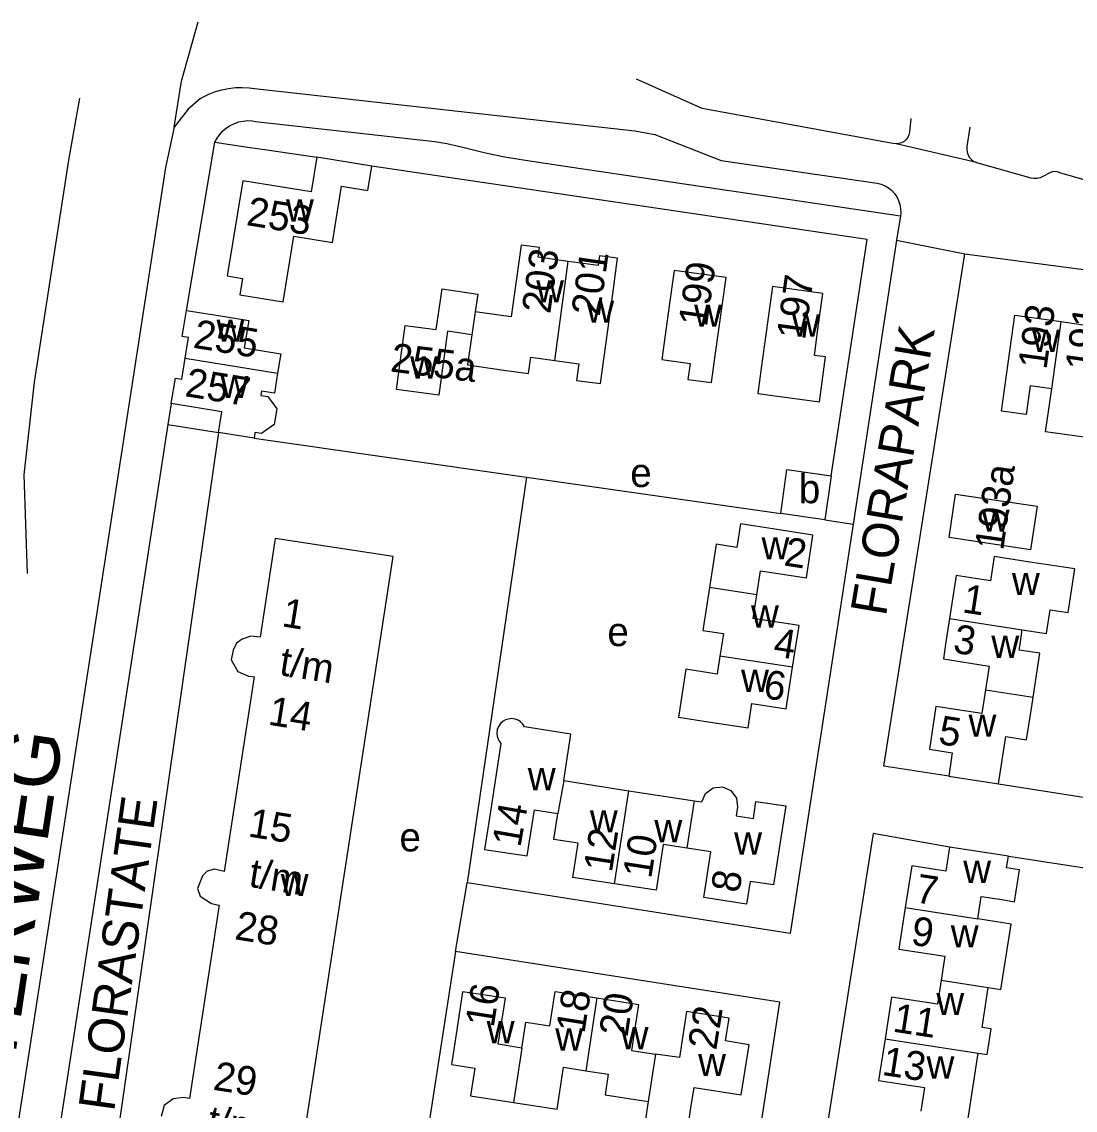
# Model space of a CAD drawing. Extents: x 161093 to 163177, y 379000 to 380904.
# Drawn here: x 161685 to 161831.1, y 380685.4 to 380836.3 of the extents above; entities that cross this region are included whole.
import ezdxf

# ---------------------------------------------------------------- set-up
doc = ezdxf.new("R2010")
doc.units = 0
for name, color, linetype in [('BLT_Basislijn', 7, 'Continuous'), ('BLT_Bebouwing', 7, 'Continuous'), ('BLT_Centroide', 7, 'Continuous'), ('BLT_Huisnummer', 7, 'Continuous'), ('BLT_Huisnummer_ tussenligend', 7, 'Continuous'), ('BLT_Huisnummer_reeks', 7, 'Continuous'), ('BLT_Onderverdeling_panden', 7, 'Continuous'), ('BLT_Straatnaam', 7, 'Continuous'), ('BLT_Straatnaam_hoofdweg', 7, 'Continuous'), ('BLT_Vlakafsluiter', 7, 'Continuous')]:
    doc.layers.add(name, color=color, linetype=linetype)

msp = doc.modelspace()

# ---------------------------------------------------------------- linework, layer by layer
at = {"layer": 'BLT_Basislijn'}
for p, q in [((161717.31, 380827.08), (161770.07, 380821.19)), ((161717.48, 380822.51), (161742.32, 380819.71)), ((161808.36, 380822.91), (161808.16, 380821.02)), ((161816.53, 380821.71), (161816.13, 380819.01)), ((161707.87, 380796.3), (161711.81, 380819.62)), ((161711.81, 380819.62), (161716.07, 380818.99)), ((161716.07, 380818.99), (161718.08, 380818.69)), ((161718.08, 380818.69), (161719.34, 380818.5)), ((161719.34, 380818.5), (161725.95, 380817.53)), ((161817.43, 380816.79), (161824.97, 380814.68)), ((161826.7, 380814.9), (161827.75, 380815.46)), ((161806.96, 380809.8), (161806.9, 380809.41)), ((161806.9, 380809.41), (161806.37, 380806.01)), ((161705.77, 380783.39), (161705.32, 380780.45)), ((161712.32, 380779.37), (161695.84, 380664.67)), ((161705.32, 380780.45), (161699.21, 380740.85)), ((161705.32, 380780.45), (161712.32, 380779.37)), ((161755.06, 380773.18), (161790.29, 380768.1)), ((161796.43, 380767.23), (161800.33, 380766.66)), ((161699.21, 380740.85), (161688.95, 380674.32)), ((161745.18, 380707.38), (161746.83, 380716.9)), ((161745.18, 380707.38), (161738.3, 380662.64))]:
    msp.add_line(p, q, dxfattribs=at)
for points in [[(161806.31, 380819.38), (161805.84, 380819.44), (161798.01, 380820.86), (161779.4, 380824.3), (161770.31, 380828.37)], [(161709.84, 380825.69), (161710.15, 380825.88), (161711, 380826.29), (161711.89, 380826.63), (161712.8, 380826.9), (161713.73, 380827.09), (161714.67, 380827.2), (161715.62, 380827.23), (161716.57, 380827.18), (161717.31, 380827.08)], [(161685.83, 380759.79), (161685.38, 380773.49), (161686.83, 380786.36), (161691.59, 380817.14), (161693.08, 380825.73)], [(161709.84, 380825.69), (161708.12, 380824.18), (161706.18, 380821.7)], [(161706.18, 380821.7), (161704.99, 380816.11), (161684.56, 380683.72)], [(161711.81, 380819.62), (161712.12, 380820.18), (161712.49, 380820.71), (161712.93, 380821.18), (161713.42, 380821.59), (161713.96, 380821.94), (161714.54, 380822.22), (161715.14, 380822.43), (161715.77, 380822.56), (161716.41, 380822.61), (161717.06, 380822.58), (161717.48, 380822.51)], [(161770.07, 380821.19), (161772.82, 380820.68), (161782.06, 380817.1), (161803.69, 380813.94)], [(161808.16, 380821.02), (161808.08, 380820.64), (161807.92, 380820.29), (161807.69, 380819.98), (161807.4, 380819.73), (161807.06, 380819.53), (161806.7, 380819.42), (161806.31, 380819.38)], [(161742.32, 380819.71), (161743.97, 380819.43), (161745.61, 380819.08), (161746.56, 380818.84)], [(161746.56, 380818.84), (161749.15, 380818.21), (161751.76, 380817.66), (161754.28, 380817.2)], [(161816.13, 380819.01), (161816.1, 380818.61), (161816.15, 380818.22), (161816.28, 380817.84), (161816.48, 380817.49), (161816.75, 380817.2), (161817.07, 380816.96), (161817.43, 380816.79)], [(161754.28, 380817.2), (161760.1, 380816.33), (161806.9, 380809.41)], [(161797.3, 380773.35), (161802.3, 380806.13), (161733.57, 380816.29)], [(161827.75, 380815.46), (161828.04, 380815.57), (161828.34, 380815.61), (161828.65, 380815.56), (161828.95, 380815.42)], [(161824.97, 380814.68), (161825.42, 380814.62), (161825.87, 380814.64), (161826.32, 380814.74), (161826.7, 380814.9)], [(161828.95, 380815.42), (161832.46, 380814.42), (161836, 380813.5), (161839.56, 380812.65), (161843.13, 380811.88), (161846.07, 380811.31)], [(161803.69, 380813.94), (161804.24, 380813.79), (161804.76, 380813.57), (161805.25, 380813.28), (161805.69, 380812.92), (161806.08, 380812.51), (161806.4, 380812.04), (161806.65, 380811.53), (161806.83, 380810.99), (161806.93, 380810.44), (161806.96, 380809.8)], [(161806.37, 380806.01), (161800.33, 380766.66)], [(161813.59, 380731.68), (161804.62, 380733.1), (161815.82, 380804.14)], [(161815.82, 380804.14), (161900, 380793.04), (161955.5, 380784.75), (162036.45, 380773.62)], [(161717.25, 380778.57), (161755.06, 380773.18)], [(161755.06, 380773.18), (161746.83, 380716.9)], [(161800.33, 380766.66), (161791.62, 380709.88), (161746.83, 380716.9)], [(161820.5, 380730.61), (161900, 380718.13), (161922.22, 380714.98)], [(161813.7, 380721.85), (161803.14, 380723.75), (161793.18, 380660.59), (161792.97, 380657.69), (161794.63, 380655.83), (161796.7, 380654.59), (161900, 380638.91), (161927.09, 380634.62), (161929.68, 380637), (161939.36, 380702.62), (161928.91, 380704.1)], [(161821.88, 380720.59), (161900, 380708.64), (161920.72, 380705.36)], [(161783.33, 380655.62), (161790.16, 380700.36), (161745.18, 380707.38)]]:
    msp.add_lwpolyline(points, dxfattribs=at)
at = {"layer": 'BLT_Bebouwing'}
for p, q in [((161733.57, 380816.29), (161725.95, 380817.53)), ((161794.96, 380790.05), (161795.46, 380793.69)), ((161797.3, 380773.35), (161796.43, 380767.23)), ((161796.43, 380767.23), (161790.29, 380768.1)), ((161813.59, 380731.68), (161820.5, 380730.61)), ((161821.88, 380720.59), (161813.7, 380721.85))]:
    msp.add_line(p, q, dxfattribs=at)
for points in [[(161725.95, 380817.53), (161725.17, 380812.73), (161715.69, 380814.28), (161713.54, 380801.07), (161715.65, 380800.73), (161715.28, 380798.47), (161721.28, 380797.49), (161721.65, 380799.75), (161722.76, 380806.57), (161728.12, 380805.7), (161729.39, 380813.51), (161733.02, 380812.92), (161733.57, 380816.29)], [(161760.84, 380803.08), (161756.65, 380803.66), (161756.84, 380805.02), (161754.3, 380805.36), (161753.62, 380800.4), (161752.93, 380795.41), (161747.92, 380796.1)], [(161758.96, 380789.36), (161762.28, 380788.9), (161761.96, 380786.59), (161765.3, 380786.14), (161767.01, 380798.58), (161767.68, 380803.54), (161765.18, 380803.88), (161764.99, 380802.52), (161760.84, 380803.08)], [(161781.22, 380790.05), (161782.75, 380800.85), (161775.51, 380801.84), (161774.84, 380796.91), (161773.82, 380789.48), (161777.74, 380788.94), (161777.43, 380786.72), (161780.71, 380786.27), (161781.22, 380790.05)], [(161738.2, 380794.21), (161742.5, 380793.63), (161743.35, 380799.27), (161748.29, 380798.53), (161747.92, 380796.1)], [(161795.46, 380793.69), (161796.14, 380798.65), (161789.15, 380799.6), (161788.51, 380794.93), (161787.6, 380788.28)], [(161707.71, 380789.65), (161708.18, 380792.53), (161707.27, 380792.68), (161707.87, 380796.3)], [(161707.87, 380796.3), (161713.22, 380795.43), (161716.52, 380794.89), (161715.9, 380791.1), (161720.96, 380790.28), (161720.87, 380789.75), (161720.52, 380787.57)], [(161827.88, 380785.42), (161824.87, 380785.84), (161824.32, 380781.84), (161820.91, 380782.31), (161822.76, 380795.63), (161829.19, 380794.74)], [(161829.19, 380794.74), (161834.14, 380794.02), (161835.63, 380793.82), (161834.94, 380788.86), (161833.78, 380780.49), (161832.63, 380780.64), (161832.36, 380778.71), (161827.04, 380779.46), (161827.88, 380785.42)], [(161747.45, 380792.91), (161744.09, 380793.41), (161742.88, 380784.53), (161736.99, 380785.33), (161738.2, 380794.21)], [(161747.45, 380792.91), (161746.87, 380788.72), (161751.92, 380788.02), (161755.34, 380787.56), (161755.65, 380789.81), (161758.96, 380789.36)], [(161787.6, 380788.28), (161787.12, 380784.78), (161795.67, 380783.61), (161796.52, 380789.85), (161794.96, 380790.05)], [(161705.77, 380783.39), (161706.35, 380786.91), (161707.24, 380786.77), (161707.71, 380789.65)], [(161720.52, 380787.57), (161720.07, 380784.82), (161718.31, 380785.1), (161718.21, 380784.51), (161719.16, 380784.36), (161720.41, 380782.62), (161720.06, 380780.47), (161718.31, 380779.21), (161717.37, 380779.36), (161717.25, 380778.57)], [(161712.32, 380779.37), (161712.79, 380782.24), (161705.77, 380783.39)], [(161717.25, 380778.57), (161712.32, 380779.37)], [(161790.29, 380768.1), (161791.16, 380774.22), (161797.3, 380773.35)], [(161786.97, 380756.85), (161787.48, 380760.16), (161793.85, 380759.19), (161794.76, 380765.12), (161789.49, 380765.93), (161784.7, 380766.67), (161784.2, 380763.41), (161781.34, 380763.85), (161780.41, 380757.85)], [(161720.2, 380764.66), (161718.11, 380750.99), (161716.79, 380751.09), (161715.61, 380750.71), (161714.83, 380750.14), (161714.37, 380749.15), (161714.07, 380747.83), (161715.01, 380746.23), (161716.48, 380745.58), (161717.26, 380745.46), (161713.12, 380718.46), (161711.79, 380718.78), (161710.77, 380718.53), (161710.09, 380717.86), (161709.4, 380716.09), (161709.79, 380715.06), (161711.37, 380714.02), (161712.41, 380713.8), (161708.3, 380686.97), (161707.46, 380687.14), (161706.04, 380686.93), (161704.8, 380686.03), (161704.38, 380684.51)], [(161721.71, 380665.43), (161736.53, 380762.16), (161720.2, 380764.66)], [(161823.79, 380752), (161827.17, 380751.48), (161827.67, 380754.75), (161830.14, 380754.37), (161831.07, 380760.43), (161824.85, 380761.39), (161819.9, 380762.15), (161819.39, 380758.8), (161814.62, 380759.53), (161813.71, 380753.55)], [(161780.41, 380757.85), (161779.49, 380751.9), (161782.35, 380751.46), (161782.13, 380750), (161781.87, 380748.34)], [(161791.95, 380746.79), (161792.84, 380752.57), (161786.47, 380753.54), (161786.97, 380756.85)], [(161813.71, 380753.55), (161813.16, 380750), (161812.85, 380747.95), (161819.22, 380746.97), (161818.71, 380743.67)], [(161825.3, 380742.66), (161826.24, 380748.74), (161823.36, 380749.18), (161823.49, 380750), (161823.79, 380752)], [(161781.87, 380748.34), (161781.49, 380745.84), (161777.12, 380746.51), (161776.1, 380739.88), (161780.83, 380739.15), (161785.77, 380738.39), (161786.29, 380741.75), (161791.06, 380741.01), (161791.95, 380746.79)], [(161818.71, 380743.67), (161818.2, 380740.38), (161811.83, 380741.35), (161810.92, 380735.42), (161814.09, 380734.93), (161813.59, 380731.68)], [(161820.5, 380730.61), (161821.51, 380737.17), (161824.39, 380736.72), (161825.15, 380741.67), (161825.3, 380742.66)], [(161760.2, 380731.07), (161761.2, 380737.53), (161754.77, 380738.52), (161754.53, 380738.9), (161754.22, 380739.22), (161753.88, 380739.45), (161753.48, 380739.59), (161753.02, 380739.67), (161752.55, 380739.62), (161752.15, 380739.5), (161751.79, 380739.31), (161751.42, 380738.98), (161751.15, 380738.58), (161750.98, 380738.15), (161750.93, 380737.66), (161750.96, 380737.24), (161751.09, 380736.84), (161751.28, 380736.49), (161751.49, 380736.24), (161750.04, 380726.8), (161749.23, 380721.53), (161755.15, 380720.62), (161756.13, 380727.02), (161759.4, 380726.51)], [(161760.2, 380731.07), (161769.24, 380729.67)], [(161769.24, 380729.67), (161778.32, 380728.28)], [(161778.32, 380728.28), (161779.36, 380728.12), (161779.88, 380729.31), (161780.92, 380730.08), (161782.21, 380730.22), (161783.39, 380729.7), (161784.16, 380728.65), (161784.3, 380727.37), (161784.12, 380726.19), (161786.5, 380725.83), (161786.86, 380728.2), (161791.01, 380727.58), (161789.31, 380716.61), (161786.04, 380717.1), (161785.56, 380713.93), (161779.64, 380714.84), (161780.62, 380721.21), (161777.31, 380721.72)], [(161767.25, 380716.74), (161761.48, 380717.63), (161762.21, 380722.4), (161758.85, 380722.91), (161759.4, 380726.51)], [(161777.31, 380721.72), (161774, 380722.23), (161773.02, 380715.86), (161767.25, 380716.74)], [(161813.7, 380721.85), (161813.21, 380718.51), (161808.46, 380719.25), (161807.57, 380713.47)], [(161817.62, 380711.92), (161818.1, 380715), (161820.95, 380714.57), (161822.73, 380714.28), (161823.41, 380718.69), (161821.63, 380718.96), (161821.88, 380720.59)], [(161807.57, 380713.47), (161806.68, 380707.69), (161813.05, 380706.71), (161812.54, 380703.39)], [(161819.08, 380702.38), (161820.83, 380702.09), (161822.25, 380711.18), (161817.62, 380711.92)], [(161812.54, 380703.39), (161812.02, 380700.08), (161805.65, 380701.06), (161804.76, 380695.28)], [(161817.67, 380693.29), (161818.93, 380693.09), (161819.49, 380696.64), (161818.22, 380696.84), (161819.08, 380702.38)], [(161754.38, 380693.98), (161751.11, 380694.5), (161752.11, 380700.88), (161746.18, 380701.78), (161745.38, 380696.51), (161744.64, 380691.68), (161747.88, 380691.18), (161747.29, 380687.34), (161753.22, 380686.43)], [(161754.38, 380693.98), (161754.95, 380697.58), (161758.28, 380697.05), (161759.03, 380701.82), (161764.8, 380700.93)], [(161764.8, 380700.93), (161770.58, 380700.04), (161769.61, 380693.66), (161772.92, 380693.15)], [(161771.92, 380686.59), (161771.19, 380681.67), (161774.3, 380681.19), (161777.52, 380683.54), (161777.85, 380685.68), (161778.28, 380688.52), (161784.82, 380687.51), (161785.92, 380694.44), (161782.64, 380694.96), (161783.14, 380698.11), (161777.21, 380699.03), (161776.24, 380692.65), (161772.92, 380693.15)], [(161804.76, 380695.28), (161803.87, 380689.49), (161810.24, 380688.51), (161809.73, 380685.21)], [(161816.27, 380684.19), (161817.67, 380693.29)], [(161753.22, 380686.43), (161759.28, 380685.51), (161760.18, 380691.32), (161763.25, 380690.84)], [(161763.25, 380690.84), (161766.38, 380690.36), (161765.94, 380687.51), (161771.92, 380686.59)]]:
    msp.add_lwpolyline(points, dxfattribs=at)
msp.add_lwpolyline([(161814.55, 380770.82), (161825.86, 380769.13), (161824.96, 380763.1), (161813.64, 380764.79)], close=True, dxfattribs=at)
at = {"layer": 'BLT_Onderverdeling_panden'}
for p, q in [((161758.96, 380789.36), (161760.84, 380803.08)), ((161747.92, 380796.1), (161747.45, 380792.91)), ((161827.88, 380785.42), (161829.19, 380794.74)), ((161707.71, 380789.65), (161720.52, 380787.57)), ((161786.97, 380756.85), (161780.41, 380757.85)), ((161813.71, 380753.55), (161823.79, 380752)), ((161791.95, 380746.79), (161781.87, 380748.34)), ((161818.71, 380743.67), (161825.3, 380742.66)), ((161760.2, 380731.07), (161759.4, 380726.51)), ((161767.25, 380716.74), (161769.24, 380729.67)), ((161777.31, 380721.72), (161778.32, 380728.28)), ((161807.57, 380713.47), (161817.62, 380711.92)), ((161812.54, 380703.39), (161819.08, 380702.38)), ((161764.8, 380700.93), (161763.25, 380690.84)), ((161804.76, 380695.28), (161817.67, 380693.29)), ((161754.38, 380693.98), (161753.22, 380686.43)), ((161772.92, 380693.15), (161771.92, 380686.59))]:
    msp.add_line(p, q, dxfattribs=at)
at = {"layer": 'BLT_Vlakafsluiter'}
for p, q in [((161817.43, 380816.79), (161806.31, 380819.38)), ((161806.37, 380806.01), (161815.82, 380804.14))]:
    msp.add_line(p, q, dxfattribs=at)
msp.add_lwpolyline([(161706.18, 380821.7), (161707.19, 380828.08), (161709.49, 380836.32)], dxfattribs=at)

# ---------------------------------------------------------------- texts
at = {"layer": 'BLT_Centroide'}
for s, p in [('w', (161721.68, 380808.62)), ('w', (161756.38, 380797.41)), ('w', (161763.33, 380794.58)), ('w', (161778.28, 380794.03)), ('w', (161712.05, 380791.94)), ('w', (161791.88, 380792.67)), ('w', (161825.16, 380790.53)), ('w', (161738.9, 380786.84)), ('w', (161712.62, 380784.12)), ('e', (161769.43, 380771.79)), ('b', (161792.81, 380769.55)), ('w', (161818.17, 380765.58)), ('w', (161787.63, 380761.75)), ('w', (161822.36, 380756.81)), ('w', (161786.18, 380752.31)), ('e', (161766.26, 380749.73)), ('w', (161819.51, 380748.09)), ('w', (161784.8, 380743.38)), ('w', (161816.34, 380737.16)), ('w', (161755.22, 380729.73)), ('w', (161763.83, 380723.89)), ('w', (161772.78, 380722.52)), ('e', (161737.42, 380721.25)), ('w', (161783.84, 380720.81)), ('w', (161815.61, 380716.88)), ('w', (161720.95, 380715.06)), ('w', (161813.88, 380707.94)), ('w', (161811.88, 380698.56)), ('w', (161749.52, 380694.64)), ('w', (161759.02, 380693.64)), ('w', (161768.09, 380693.81)), ('w', (161778.84, 380690.09)), ('w', (161810.52, 380689.75))]:
    msp.add_text(s, height=4, dxfattribs=at).set_placement(p)
at = {"layer": 'BLT_Huisnummer'}
for s, rotation, p in [('253', 350.7532, (161716.07, 380808.14)), ('203', 82.205, (161758.33, 380795.73)), ('201', 81.9219, (161765.19, 380795.39)), ('199', 81.9219, (161780.05, 380793.91)), ('197', 82.2103, (161793.67, 380792.09)), ('193', 82.1011, (161827.14, 380787.98)), ('191', 82.1094, (161833.68, 380787.72)), ('255', 350.7714, (161708.69, 380791.13)), ('255a', 352.7714, (161736.05, 380787.83)), ('257', 350.7651, (161707.55, 380784.41)), ('193a', 82.1011, (161821.15, 380762.88)), ('2', 351.337, (161790.62, 380760.93)), ('1', 351.273, (161815.36, 380754.43)), ('6', 351.2249, (161787.75, 380742.55)), ('5', 351.2158, (161812.03, 380736.18)), ('14', 80.053, (161754.19, 380721.72)), ('10', 81.2401, (161772.33, 380717.38)), ('8', 81.1852, (161784.55, 380715.4)), ('7', 351.2303, (161808.85, 380714.21)), ('16', 81.0741, (161750.48, 380696.73)), ('20', 81.3503, (161769.04, 380695.43)), ('22', 81.0012, (161781.35, 380693.59)), ('11', 351.2521, (161805.71, 380696.28))]:
    msp.add_text(s, height=4, rotation=rotation, dxfattribs=at).set_placement(p)
at = {"layer": 'BLT_Huisnummer_ tussenligend'}
for s, rotation, p in [('3', 351.273, (161814.08, 380748.84)), ('4', 351.337, (161789.14, 380748.35)), ('12', 81.2401, (161766.88, 380718.23)), ('9', 351.2303, (161808.23, 380708.34)), ('18', 81.0741, (161763.06, 380695.9)), ('13', 351.2521, (161804.22, 380690.27))]:
    msp.add_text(s, height=4, rotation=rotation, dxfattribs=at).set_placement(p)
at = {"layer": 'BLT_Huisnummer_reeks'}
for s, rotation, p in [('1', 350.8518, (161720.98, 380752.49)), ('t/m', 350.8518, (161720.64, 380745.73)), ('14', 350.8518, (161719.08, 380738.85)), ('15', 350.8518, (161716.31, 380723.34)), ('t/m', 350.8518, (161716.4, 380716.38)), ('28', 350.8518, (161714.45, 380709.09)), ('29', 350.8521, (161711.45, 380688.22)), ('t/m', 350.8518, (161710.63, 380682.1))]:
    msp.add_text(s, height=4, rotation=rotation, dxfattribs=at).set_placement(p)
at = {"layer": 'BLT_Straatnaam'}
for s, rotation, p in [('FLORAPARK', 80.3093, (161804.87, 380753.75)), ('FLORASTATE', 82.0708, (161697.84, 380685.07))]:
    msp.add_text(s, height=5, rotation=rotation, dxfattribs=at).set_placement(p)
at = {"layer": 'BLT_Straatnaam_hoofdweg'}
msp.add_text('AALSTERWEG', height=8, rotation=81.4709, dxfattribs=at).set_placement((161679.81, 380664.08))

doc.saveas('drawing.dxf')
